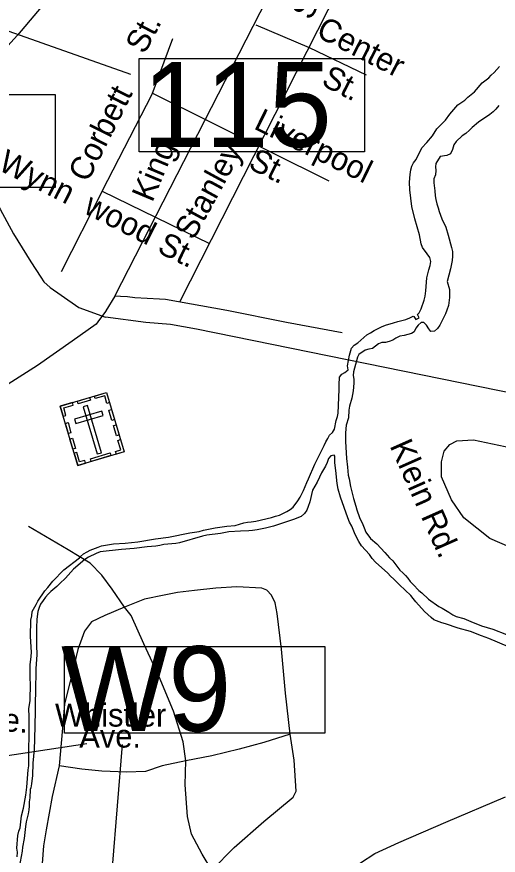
# Model space of a CAD drawing. Extents: x 2290055 to 2389491, y 66597 to 237875.
# Drawn here: x 2322219 to 2324203, y 181498 to 184954 of the extents above; entities that cross this region are included whole.
import ezdxf

# ---------------------------------------------------------------- set-up
doc = ezdxf.new("R2010")
doc.units = 0
for name, color, linetype in [('Exist Cultural Cemetery CELL', 7, 'Continuous'), ('Exist Hydrographic Creek Double Shore', 7, 'Continuous'), ('Exist Railroad Mainline', 7, 'Continuous'), ('Exist Road Non-System Type 51', 7, 'Continuous'), ('Exist Road Non-System Type 51 Label', 7, 'Continuous'), ('Exist Road Primary US Structure NCDOT Private Pedestrian CELL', 7, 'Continuous'), ('Exist Road Primary US Structure Standard Bridge Number Label', 7, 'Continuous')]:
    doc.layers.add(name, color=color, linetype=linetype)

msp = doc.modelspace()

# ---------------------------------------------------------------- linework, layer by layer
at = {"layer": 'Exist Cultural Cemetery CELL'}
for points in [[(2322398.2, 183349), (2322589.1, 183405.4), (2322661.2, 183161.2), (2322470.3, 183104.8)], [(2322469.2, 183370), (2322518.9, 183384.7), (2322522.1, 183373.7), (2322472.4, 183359)], [(2322601.5, 183363.8), (2322590.6, 183360.6), (2322581.5, 183391.5), (2322542.6, 183380), (2322539.4, 183390.7), (2322589.2, 183405.4)], [(2322410.4, 183307.5), (2322421.3, 183310.7), (2322412.2, 183341.6), (2322451.1, 183353), (2322448, 183363.7), (2322398.2, 183349)], [(2322511, 183351.8), (2322493.1, 183346.5), (2322550.6, 183152), (2322568.5, 183157.3)], [(2322456.6, 183295.3), (2322461.9, 183277.4), (2322574.8, 183310.7), (2322569.5, 183328.6)], [(2322611.2, 183290.5), (2322598.9, 183332.1), (2322609.9, 183335.3), (2322622.1, 183293.7)], [(2322431.4, 183236.3), (2322419.2, 183277.9), (2322430.1, 183281.1), (2322442.3, 183239.6)], [(2322629.9, 183227.3), (2322617.6, 183268.8), (2322628.5, 183272), (2322640.8, 183230.5)], [(2322450.5, 183171.9), (2322438.2, 183213.4), (2322449.1, 183216.6), (2322461.4, 183175.1)], [(2322629.5, 183151.8), (2322626.2, 183162.8), (2322647.3, 183169.1), (2322635.9, 183207.8), (2322646.5, 183211), (2322661.2, 183161.2)], [(2322502, 183114.2), (2322498.7, 183125.2), (2322477.7, 183119), (2322466.2, 183157.8), (2322455.5, 183154.6), (2322470.2, 183104.8)], [(2322522.2, 183132.1), (2322603.5, 183156.1), (2322606.8, 183145.2), (2322525.4, 183121.2)]]:
    msp.add_lwpolyline(points, close=True, dxfattribs=at)
at = {"layer": 'Exist Hydrographic Creek Double Shore'}
for points in [[(2323677.5, 183651.2), (2323691.7, 183661), (2323721.7, 183676.1), (2323739, 183682.8), (2323771.2, 183692), (2323789.2, 183697.9), (2323823, 183705.9), (2323839, 183712.9), (2323852.2, 183720.7), (2323855.5, 183718.8), (2323863.5, 183706), (2323877, 183712.8), (2323870.5, 183726.7), (2323877, 183734.3), (2323885.7, 183750.2), (2323898.5, 183785.6), (2323902, 183802.9), (2323905, 183824), (2323907.5, 183860.3), (2323909.5, 183878), (2323918, 183911.7), (2323923.5, 183928.8), (2323925.2, 183946), (2323921, 183961.3), (2323910.5, 183977.6), (2323890.7, 184003.2), (2323886, 184018.9), (2323879.5, 184054.9), (2323859.5, 184121.8), (2323848, 184171.8), (2323839.7, 184241.1), (2323838.2, 184272.4), (2323840.5, 184304.4), (2323842.7, 184323.1), (2323847, 184338.8), (2323853.7, 184352.4), (2323864.7, 184366.4), (2323888.5, 184414.7), (2323909.5, 184436.6), (2323932.5, 184464.2), (2323950.7, 184492.2), (2323973.5, 184516.3), (2323986.7, 184527.5), (2324004, 184553.3), (2324036.5, 184591), (2324065.7, 184611.2), (2324078.2, 184623.5), (2324106, 184644.7), (2324136.7, 184682.6), (2324164.2, 184703.2), (2324174.5, 184714.3), (2324186.7, 184724.4), (2324208.2, 184750)], [(2324205.5, 184588.5), (2324194, 184573.4), (2324183.2, 184562.1), (2324168.2, 184551), (2324122.5, 184519.9), (2324096.2, 184498.3), (2324085.2, 184486.4), (2324069.5, 184472.9), (2324054.2, 184463), (2324030.2, 184439.9), (2324020.7, 184427), (2324014.5, 184407.1), (2324006.5, 184389.6), (2323992, 184381.9), (2323964, 184377.7), (2323945.7, 184349.4), (2323945.2, 184336.1), (2323946.5, 184321.1), (2323944.5, 184303), (2323937.7, 184286.7), (2323938.2, 184269.2), (2323942.7, 184236.6), (2323944.2, 184216.3), (2323946.5, 184200.5), (2323950.2, 184182.7), (2323956, 184166.7), (2323959.7, 184151.5), (2323971.5, 184121.4), (2323987, 184087.4), (2323997.5, 184054), (2324010.7, 184003.7), (2324014.5, 183986.5), (2324015.2, 183967.9), (2324013, 183949.7), (2324006.5, 183914.9), (2323993.5, 183862.6), (2324002, 183829.7), (2324003, 183812.8), (2324002.7, 183796.4), (2323998, 183763.8), (2323992, 183745.3), (2323985.5, 183729.2), (2323978, 183712.6), (2323962.5, 183682.8), (2323953.2, 183669.1), (2323941, 183658.2), (2323926.2, 183657), (2323917, 183667.4)], [(2323917, 183667.4), (2323907.7, 183683), (2323896.5, 183693.8), (2323886, 183693.3), (2323873, 183683), (2323864.2, 183670.1), (2323857, 183655), (2323845.7, 183648.1), (2323815.7, 183640.3), (2323798, 183637), (2323782, 183629.4), (2323769, 183621.1), (2323754.2, 183615.4), (2323739, 183611.1), (2323724, 183611.6), (2323709.5, 183605.7), (2323685, 183587.1), (2323669.7, 183584.3), (2323655, 183579.4), (2323629.2, 183561.5), (2323623.2, 183551.5), (2323607.5, 183491.1), (2323605.7, 183475.7), (2323608, 183460.6), (2323608.5, 183444.3), (2323606, 183412.8), (2323599.5, 183381.7), (2323591, 183349.3), (2323588.2, 183333), (2323586.7, 183300.6), (2323576.5, 183270.2), (2323573.7, 183238.6), (2323573.7, 183203.9), (2323578.5, 183132.9), (2323582.5, 183097.5), (2323584.5, 183065.1), (2323588.5, 183049.5), (2323594.2, 183017.9), (2323606.5, 182969), (2323616.2, 182937.3), (2323620, 182921.4), (2323631.7, 182890), (2323645.5, 182861.7), (2323651.5, 182847.2), (2323657.2, 182830.2), (2323677, 182804), (2323702.5, 182781.8), (2323735.5, 182746.1), (2323755, 182723.1), (2323768.5, 182711.6), (2323797.5, 182672.7), (2323809.7, 182662.3), (2323821, 182650.7), (2323831.2, 182639.3), (2323840.5, 182625.7), (2323853.5, 182614.5), (2323876, 182588.9), (2323888, 182579.4), (2323915.7, 182553.3), (2323958.5, 182522.7), (2323972.5, 182515.7), (2324000, 182499.4), (2324016, 182488.8), (2324030.2, 182482.4), (2324061.5, 182474), (2324090, 182461.6), (2324134.7, 182443.9), (2324181.2, 182429), (2324293.5, 182386)], [(2322220.5, 181490.9), (2322221.2, 181509.9), (2322219.7, 181527.2), (2322220.2, 181545), (2322222.2, 181561.6), (2322223.2, 181578.4), (2322227.2, 181596.2), (2322232.2, 181610.5), (2322239, 181659.8), (2322246.5, 181691.2), (2322256.2, 181745.2), (2322260.5, 181778.8), (2322266, 181849.3), (2322268.2, 181866.2), (2322269, 181883.5), (2322268.7, 181953.5), (2322269.7, 181970.7), (2322270, 182020.4), (2322269.7, 182069.2), (2322268.5, 182101.9), (2322273.5, 182135.5), (2322275.5, 182206.2), (2322274.7, 182225.4), (2322274.7, 182264.1), (2322273.7, 182282.3), (2322278.2, 182316.8), (2322279, 182334.2), (2322275.7, 182399.3), (2322276.5, 182467.4), (2322280.5, 182484.6), (2322282.2, 182502.7), (2322298.5, 182530.9), (2322306, 182545.6), (2322335, 182588.4), (2322347, 182601.1), (2322368, 182627.1), (2322412.7, 182674), (2322477.5, 182724.1), (2322481.7, 182729.6), (2322494.5, 182739.6), (2322508.5, 182748.7), (2322521.7, 182755.6), (2322554, 182768.2), (2322568.7, 182773), (2322584.5, 182776.5), (2322618.2, 182781.1), (2322666, 182783.9), (2322717.5, 182789.1), (2322791, 182801.9), (2322844.7, 182809.1), (2322932.2, 182827.3), (2322951, 182829.2), (2322970.7, 182832.5), (2322988.5, 182837.7), (2323037, 182847.7), (2323085, 182854.2), (2323119, 182856.8), (2323154.2, 182867.4), (2323170, 182870.5), (2323185.2, 182871.7), (2323204, 182874.6), (2323269.2, 182890.4), (2323285.5, 182895.8), (2323301.7, 182900.1), (2323331.5, 182914.8), (2323345.7, 182922.7), (2323358.7, 182933.2), (2323377.2, 182959), (2323386.7, 182973.7), (2323400.7, 183001.3), (2323414.2, 183033.7), (2323421.7, 183048.8), (2323447.2, 183109.5), (2323486.2, 183186.3), (2323493.2, 183201.6), (2323501.7, 183215.3), (2323508.5, 183228.9), (2323520.2, 183241.1), (2323529, 183254.6), (2323535.5, 183289.4), (2323541, 183305.8), (2323543.2, 183320.8), (2323548, 183417.1), (2323547.5, 183436.5), (2323548.5, 183468.5), (2323558.2, 183480.5), (2323571.7, 183488.4), (2323584.7, 183499.5), (2323581.5, 183514.8), (2323590.7, 183558.7), (2323598.5, 183588.8), (2323610, 183600), (2323624.5, 183610.5), (2323661.5, 183643.4), (2323677.5, 183651.2)], [(2324245.2, 182356.5), (2324165.2, 182391.1), (2324134.2, 182401.9), (2324088.7, 182419.7), (2324039, 182433.9), (2323986.7, 182451.6), (2323971, 182455.7), (2323938.7, 182468.8), (2323926.5, 182477.7), (2323900.2, 182502), (2323863.5, 182542.1), (2323853.5, 182556.2), (2323843.7, 182568), (2323820.5, 182590.9), (2323796.2, 182612.9), (2323772.5, 182636.4), (2323759.7, 182647.6), (2323748.2, 182660.1), (2323697.2, 182705.7), (2323684.2, 182721), (2323672.5, 182736.9), (2323640.5, 182773.5), (2323629.5, 182790.9), (2323614, 182820.2), (2323599.5, 182854.8), (2323590.5, 182871.1), (2323583, 182888.5), (2323553.5, 182974.3), (2323544, 183006.4), (2323539.5, 183029.7), (2323534.7, 183083.9), (2323530.5, 183115.6), (2323530.5, 183143.4), (2323527.5, 183147.4), (2323513.2, 183144.7), (2323504.5, 183132.7), (2323499, 183116.4), (2323491.7, 183101.7), (2323475, 183073.8), (2323467.2, 183056), (2323457.2, 183036), (2323447, 183019), (2323438.5, 183002.2), (2323426.5, 182954.7), (2323420.5, 182935.4), (2323414, 182919.9), (2323405, 182906.3), (2323391.5, 182894.4), (2323360, 182882.3), (2323277, 182854.5), (2323260.5, 182849.6), (2323243.5, 182845.6), (2323209.7, 182838.7), (2323190.5, 182835.8), (2323175, 182834.6), (2323141.2, 182833.8), (2323092.5, 182830.8), (2323058.5, 182823.6), (2323002.7, 182817.4), (2322984.2, 182813.6), (2322889.7, 182786), (2322874, 182783.5), (2322825.5, 182778.1), (2322808, 182774.6), (2322792.5, 182772.5), (2322755.7, 182769), (2322702.2, 182761.9), (2322650.5, 182758.5), (2322562.2, 182748.3), (2322545.5, 182741.4), (2322514.5, 182726), (2322499, 182716.7), (2322452, 182676.4), (2322420, 182639.3), (2322396.5, 182618.2), (2322384.5, 182605.7), (2322359.7, 182585.5), (2322347.7, 182574), (2322337, 182561.4), (2322328, 182547.7)], [(2322328, 182547.7), (2322317, 182533.3), (2322310.5, 182519.2), (2322305.7, 182502.1), (2322302, 182471.2), (2322300.5, 182434.9), (2322300.2, 182362.4), (2322301, 182324.6), (2322297.5, 182266.7), (2322296.7, 182169.5), (2322295.2, 182130.3), (2322295, 182091.2), (2322292, 181975.4), (2322290, 181934.6), (2322285.5, 181877.8), (2322283.5, 181826.5), (2322280.2, 181791.7), (2322277.2, 181776), (2322274.2, 181769.3), (2322272.5, 181734.2), (2322270.2, 181718.3), (2322270, 181700.2), (2322268.2, 181684.9), (2322265.5, 181667.8), (2322257.5, 181634.8), (2322254.7, 181616.3), (2322249.2, 181566.2), (2322242.5, 181530.3), (2322240.5, 181513.8), (2322228.2, 181448.3)]]:
    msp.add_lwpolyline(points, dxfattribs=at)
at = {"layer": 'Exist Railroad Mainline'}
for points in [[(2323165.9, 186185.4), (2323158.2, 186174.2), (2323033.5, 185992.1), (2322674, 185462.1), (2322538.2, 185276.8), (2322386.1, 185074.7), (2322221.9, 184878.3), (2321967.4, 184599.4)], [(2321579.4, 184417.2), (2321704.7, 184417.2), (2321829.9, 184404.2), (2321927.5, 184368.4), (2322036.4, 184296.8), (2322103.1, 184233.4), (2322148.9, 184161.2), (2322205.6, 184060.2), (2322277.2, 183944.7), (2322317.8, 183881.3), (2322329.7, 183861.6), (2322356.6, 183838.6), (2322402.4, 183806.5), (2322474, 183756.1), (2322584.5, 183715.4)], [(2326336.6, 182931.8), (2326093.9, 182986.6), (2325764.5, 183094.8), (2325672.9, 183114.4), (2322960.2, 183666.6), (2322852.9, 183686.1), (2322750.4, 183694.2), (2322584.5, 183715.4)]]:
    msp.add_lwpolyline(points, dxfattribs=at)
at = {"layer": 'Exist Road Non-System Type 51'}
msp.add_line((2322623.6, 183803), (2322586.2, 183741.5), dxfattribs=at)
for points in [[(2322623.6, 183803), (2323392, 185306.3)], [(2323589.1, 185156.1), (2322890, 183777.7)], [(2323204.3, 184921.3), (2323424.8, 184827.4)], [(2322777.3, 184634.9), (2322861.8, 184864.9)], [(2323424.8, 184827.4), (2323659.5, 184714.7)], [(2322570.9, 184235.7), (2322777.3, 184634.9)], [(2322778.8, 184638.9), (2323504.6, 184278)], [(2322570.9, 184235.7), (2322401.9, 183902.4)], [(2322570.9, 184235.7), (2323012.8, 184019.8)], [(2322831.9, 183788.2), (2322807.2, 183789.5), (2322705.1, 183795.6), (2322675.1, 183799.2), (2322647, 183800.7), (2322623.6, 183803)], [(2323560, 183651.8), (2323330.2, 183694.5), (2323084.1, 183742.9), (2322831.9, 183788.2)], [(2322586.2, 183741.5), (2322586, 183741.2), (2322559.9, 183706)], [(2322559.9, 183706), (2322546.1, 183687.4), (2322446.8, 183617.5), (2322304.8, 183516.1), (2322183.8, 183439.1), (2322112.2, 183382.1), (2322058.9, 183360.3), (2321973.8, 183338.9), (2321880.4, 183319.1), (2321838.8, 183307.3), (2321811.8, 183286.2), (2321795.1, 183251.7), (2321786.6, 183167.4), (2321771.8, 182986.6), (2321763.2, 182846.1), (2321755.8, 182675.8)], [(2324525.6, 182705.4), (2324382.1, 182739.8), (2324261.4, 182763.2), (2324169.5, 182803.6), (2324062.1, 182889.3), (2324011.3, 182963.4), (2323969.5, 183057.6), (2323969, 183119.6), (2323981.3, 183164), (2324004.2, 183191.2), (2324033.5, 183206.1), (2324101.6, 183210.8), (2324258.8, 183177.3), (2324466.7, 183131.4), (2324687.1, 183078.1), (2324952.4, 182991.2), (2325173.5, 182936.8), (2325502.3, 182867.3)], [(2322662.3, 182519.7), (2322611.4, 182593.9), (2322569, 182652.2), (2322521.1, 182702.2), (2322431, 182756.7), (2322267.1, 182852.3)], [(2323345.2, 181996.7), (2323326.7, 182166), (2323309.4, 182347.5), (2323291.7, 182494.8), (2323283.8, 182538.4), (2323268.7, 182569.7), (2323249.8, 182590.9), (2323229.5, 182598.3), (2323125.3, 182604), (2323039.5, 182598.7), (2322951.6, 182589.3), (2322882, 182580.6), (2322826.3, 182570.2), (2322745, 182552.9), (2322662.3, 182519.7)], [(2322662.3, 182519.7), (2322581.5, 182486.7), (2322526.8, 182460.2), (2322498.1, 182421.3), (2322471.2, 182346.1), (2322441.9, 182224.8), (2322416.1, 182121.7), (2322407.9, 182021.7), (2322394, 181866.9)], [(2322915.4, 181887.5), (2322904.4, 181965.2), (2322865.3, 182091.6), (2322805.9, 182233.3), (2322742.4, 182369), (2322689.8, 182486.7), (2322662.3, 182519.7)], [(2323345.2, 181996.7), (2323236.7, 181962.2), (2323135.7, 181934.3), (2323022.9, 181907.8), (2322915.4, 181887.5)], [(2323023.5, 181435.6), (2323115.6, 181529.5), (2323237.4, 181636.4), (2323357.5, 181737), (2323370.6, 181761.4), (2323361.7, 181889.1), (2323345.2, 181996.7)], [(2322394, 181866.9), (2322365.3, 181739.7), (2322340.5, 181602.8), (2322329.4, 181536.1), (2322324, 181464), (2322330.4, 181402.2), (2322333.4, 181326.2), (2322333.3, 181230.4), (2322326.4, 181154), (2322332.3, 181104.3), (2322364.2, 181055.4), (2322403.4, 181025.1), (2322436.2, 181010.3), (2322474.2, 181003.9), (2322515.9, 181009.5), (2322559.7, 181023.1), (2322627.5, 181076), (2322735.4, 181178.4), (2322868.6, 181303.4), (2323023.5, 181435.6)], [(2322915.4, 181887.5), (2322818.4, 181865.6), (2322749.1, 181842.8), (2322671.5, 181839.8), (2322569.2, 181843.9), (2322486.8, 181852.5), (2322394, 181866.9)], [(2323023.5, 181435.6), (2322982.8, 181502.2), (2322939.5, 181584.5), (2322922.5, 181657.7), (2322913.4, 181787.3), (2322915.4, 181887.5)], [(2323560, 180666.6), (2323542.5, 180802.1), (2323545, 180946.2), (2323550.3, 181110.5), (2323565.7, 181279.2), (2323577.5, 181385.7), (2323597.7, 181430.4), (2323636.4, 181466.1), (2323694.9, 181504.2), (2323793.2, 181550.1), (2323987.8, 181633.9), (2324233.7, 181737.9)]]:
    msp.add_lwpolyline(points, dxfattribs=at)
at = {"layer": 'Exist Road Non-System Type 51 Label'}
msp.add_lwpolyline([(2322507.1, 181957.3), (2322043.7, 181887.3)], dxfattribs=at)
at = {"layer": 'Exist Road Primary US Structure NCDOT Private Pedestrian CELL'}
msp.add_lwpolyline([(2322415.1, 182358.9), (2323489.3, 182358.9), (2323489.3, 182001), (2322415.1, 182001)], close=True, dxfattribs=at)
msp.add_lwpolyline([(2322584.3, 179000.4), (2322489.1, 179931.3), (2322654.7, 181953.9)], dxfattribs=at)
at = {"layer": 'Exist Road Primary US Structure Standard Bridge Number Label'}
msp.add_line((2320399.8, 185523.4), (2322687.2, 184718.4), dxfattribs=at)
for points in [[(2322724, 184782.2), (2323652.9, 184782.2), (2323652.9, 184398.1), (2322724, 184398.1)], [(2321448, 184634.5), (2322377, 184634.5), (2322377, 184250.4), (2321448, 184250.4)]]:
    msp.add_lwpolyline(points, close=True, dxfattribs=at)

# ---------------------------------------------------------------- texts
at = {"layer": 'Exist Road Non-System Type 51 Label'}
for s, rotation, p in [('St.', 63.9805, (2323431, 184936.6)), ('Center', 332.8069, (2323447.7, 184875.6)), ('St.', 62.0656, (2322745.7, 184796.6)), ('St.', 332.8069, (2323469.9, 184674.9)), ('Corbett', 63.3523, (2322511.1, 184267.5)), ('Liverpool', 333.6387, (2323191.2, 184494.8)), ('King', 67.2644, (2322777.2, 184185.9)), ('Stanley', 61.4107, (2322947.7, 184029.7)), ('Wynn  wood', 333.1893, (2322137, 184325.7)), ('St.', 333.6387, (2323168.5, 184331.8)), ('St.', 333.6121, (2322793.2, 183985.7)), ('Klein Rd.', 293.9345, (2323754.6, 183186.2)), ('Park Ave.', 355.1007, (2321714.7, 182048.3))]:
    msp.add_text(s, height=95, rotation=rotation, dxfattribs=at).set_placement(p)
for s, p in [('Whistler', (2322376.3, 182028)), ('Ave.', (2322476.6, 181941.5))]:
    msp.add_text(s, height=95, dxfattribs=at).set_placement(p)
at = {"layer": 'Exist Road Primary US Structure NCDOT Private Pedestrian CELL'}
msp.add_text('W9', height=350, dxfattribs=at).set_placement((2322401.2, 182009.3))
at = {"layer": 'Exist Road Primary US Structure Standard Bridge Number Label'}
msp.add_text('115', height=350, dxfattribs=at).set_placement((2322736.5, 184417.9))

doc.saveas('drawing.dxf')
